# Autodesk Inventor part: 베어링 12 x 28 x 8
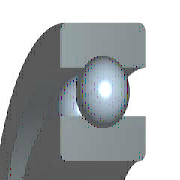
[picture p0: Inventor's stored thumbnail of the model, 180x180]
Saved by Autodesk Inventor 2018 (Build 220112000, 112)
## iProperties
IsCustomPart: 1
Created: 2012-02
Part Number: 베어링 12 x 28 x 8
Material: 강철, 연강
Description: 깊은 그루브 볼 베어링
Document SubType Name: Modeling
Standard: KS B 2023
Designer: mduedu
Standards Organization: KS
Language: ko-KR
Size Designation: 6001 - 12 x 28 x 8
Categories: <MemberInstance><Categories><Category DisplayName="샤프트 부품" InternalName="7f7aeb1f-a693-4053-b835-cee3144e0d98" Mnemonic="SHFT"><Category DisplayName="베어링" Inter
Density: 7.85 g/cm^3
Appearance: 노란색
Mass: 21.4581 g
Surface Area: 31.1809 cm^2
Volume: 2.73351 cm^3
Author: mduedu
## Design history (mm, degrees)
sketch "스케치" dims "d0" = 4.16 (= -0.26 x WD + 0.26 x BD)
  geometry: L1 (1.92, 10)-(6.08, 10); L2 (4, 10)-(4, 7.92); L3 (4, 10)-(4, 12.08); L4 (2.454, 8.608)-(0, 8.608); L5 (0, 6)-(8, 6); L6 (2.454, 11.392)-(0, 11.392); L7 (0, 14)-(8, 14); L8 (8, 6)-(8, 8.608); L9 (5.546, 8.608)-(8, 8.608); L10 (5.546, 11.392)-(8, 11.392); L11 (8, 14)-(8, 11.392); L12 (-1.4, 0)-(8.4, 0) reference; L13 (0, -0.3)-(0, 5.3) reference
  constraints: 22 end point, 4 point on line, 2 collinear, 2 perpendicular, 2 symmetric about line, 1 midpoint, 1 parallel, 14 other
  dimensions: "d9" = 12 diameter of L5 L12 (= WD); "d11" = 28 diameter of L7 L12 (= BD); "d12" = 8 distance between parallel lines of L8 L13 (= KB); "d13" = 17.216 diameter of L9 L12 (= 0.326 x BD + 0.674 x WD)
revolve "본체" stored, may be unused: angle "d6" = 90 deg
revolve "볼" stored, may be unused: angle "d7" = 90 deg
pattern_circular "IDS_ARRAYBALL[SIMPL:T]" dims angle "d3" = 360 deg
body "Solid1"
fillet "모깎기1" dims "d1" = 0.3 (= KRS)
other parameters: "WD" = 12 [user parameter; used in 5 equation terms], "BD" = 28 [user parameter; used in 5 equation terms], "KB" = 8 [user parameter; used in 1 equation term], "KRS" = 0.3 [user parameter; used in 1 equation term], "d4" = 0, "d5" = 0, "d8" = 0, "d14" = 0, "d15" = 0, "BBA" = 0 [user parameter], "BC0" = 2360000 [user parameter], "BC" = 5070000 [user parameter], "BR" = 14 (= 0.5 x BD) [user parameter], "WR" = 6 (= 0.5 x WD) [user parameter]
